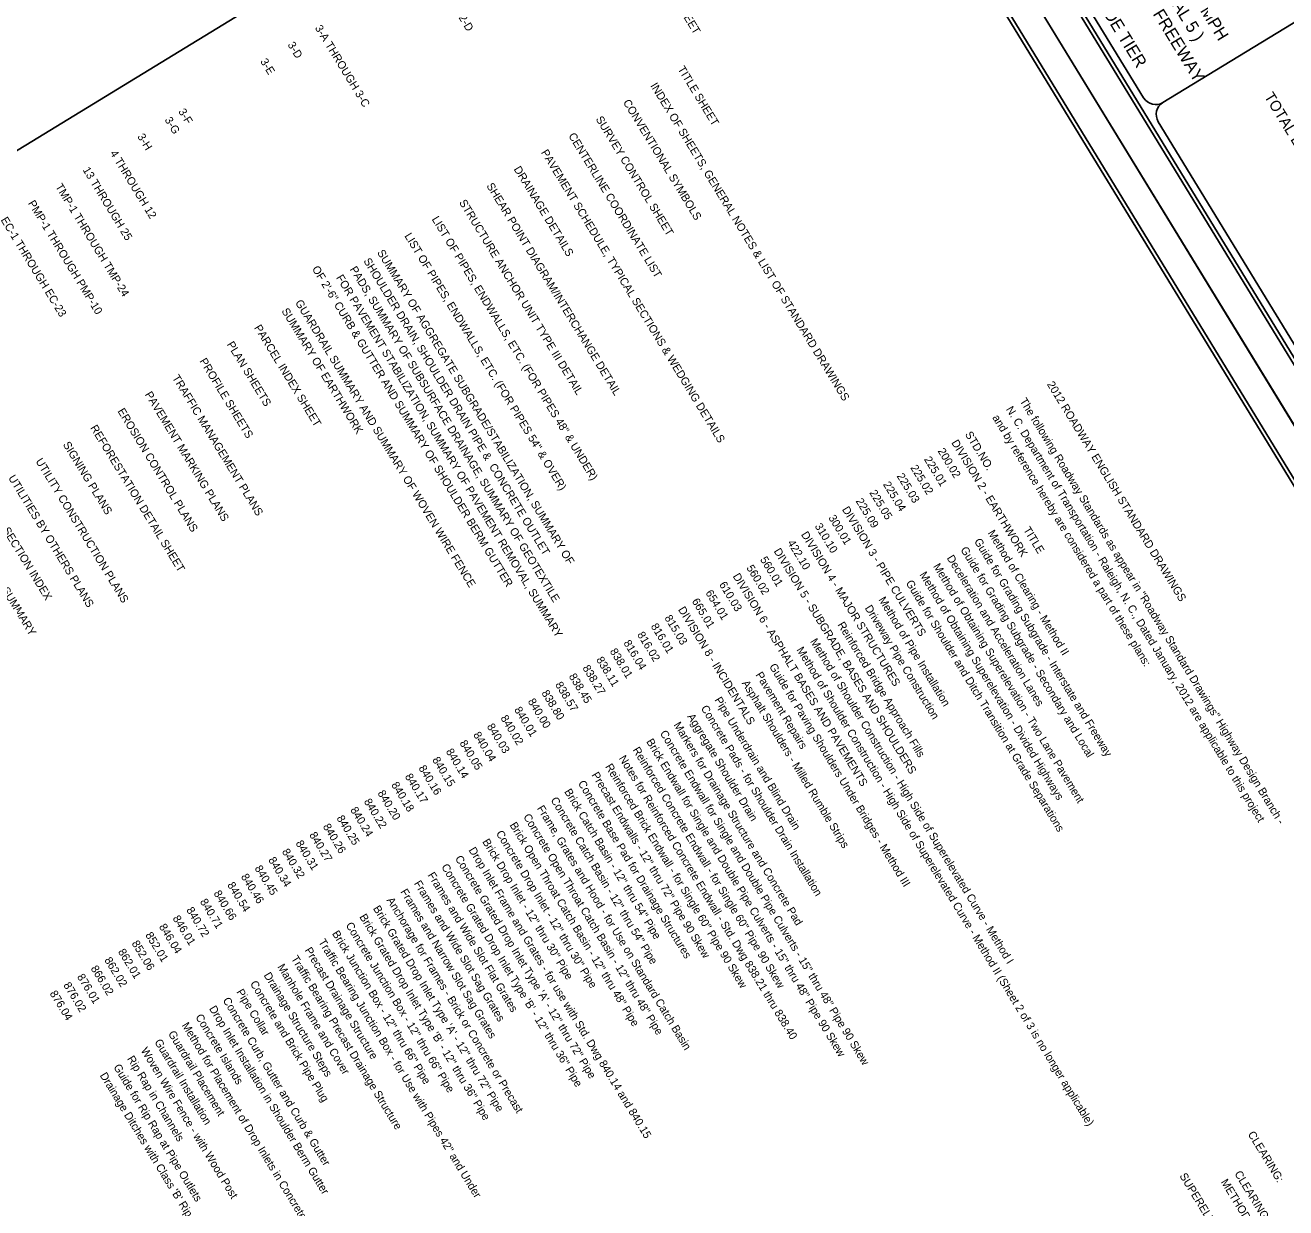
# Model space of a CAD drawing. Extents: x 1750583 to 1791140, y 783580 to 827376.
# Drawn here: x 1765888 to 1775731, y 806485 to 815720 of the extents above; entities that cross this region are included whole.
import ezdxf

# ---------------------------------------------------------------- set-up
doc = ezdxf.new("R2010")
doc.units = 0
for name, color, linetype in [('Prop Dimension Text', 7, 'Continuous'), ('Sheet Cutting Line CELL', 7, 'Continuous'), ('Sheet Data Field CELL', 7, 'Continuous'), ('Sheet Plan CELL', 7, 'Continuous'), ('Sheet Plot Border Inside CELL', 7, 'Continuous'), ('Sheet Plot Border Outside CELL', 7, 'Continuous'), ('Sheet Symbology CELL', 7, 'Continuous'), ('Sheet Title CELL', 7, 'Continuous')]:
    doc.layers.add(name, color=color, linetype=linetype)

msp = doc.modelspace()

# ---------------------------------------------------------------- linework, layer by layer
at = {"layer": 'Sheet Cutting Line CELL'}
for p, q in [((1771176.2, 820157.4), (1780824.8, 804365.9)), ((1780822, 804370.5), (1771176.2, 820157.4))]:
    msp.add_line(p, q, dxfattribs=at)
at = {"layer": 'Sheet Plan CELL'}
msp.add_lwpolyline([(1780513.6, 804401), (1771919.2, 818467.1), (1762073, 812451), (1770667.3, 798385)], close=True, dxfattribs=at)
at = {"layer": 'Sheet Plot Border Inside CELL'}
for points in [[(1771461.1, 820164), (1781009.5, 804536.6), (1790903.5, 810581.9), (1781355.2, 826209.3)], [(1761170, 813876.1), (1770715.5, 798253.4), (1780608.6, 804298.1), (1771063.2, 819920.9)]]:
    msp.add_lwpolyline(points, close=True, dxfattribs=at)
at = {"layer": 'Sheet Plot Border Outside CELL'}
for points in [[(1791139.8, 810668.3), (1781491.2, 826459.8), (1771176.2, 820157.4), (1780824.8, 804365.9)], [(1760908, 813883.5), (1770553.7, 798096.7), (1780822, 804370.5), (1771176.2, 820157.4)]]:
    msp.add_lwpolyline(points, close=True, dxfattribs=at)
at = {"layer": 'Sheet Title CELL'}
msp.add_line((1776271.7, 816033.2), (1774771.3, 815116.5), dxfattribs=at)
for points in [[(1772424.7, 818640.7), (1780904.5, 804762.2)], [(1773789.5, 816512.7), (1774620.3, 815152.9)], [(1774734.7, 814965.3), (1776912, 811401.9)]]:
    msp.add_lwpolyline(points, dxfattribs=at)
for centre, start, end in [((1774714.5, 815210.4), 211.42495, 301.42495), ((1774829.1, 815022.9), 121.42495, 211.42495)]:
    msp.add_arc(centre, 109.9, start, end, dxfattribs=at)

# ---------------------------------------------------------------- texts
at = {"layer": 'Prop Dimension Text'}
for s, p in [('SHEET NUMBER                            SHEET', (1770280.9, 817002.1)), ('2 THROUGH 2-D', (1769000.9, 816220)), ('3-A THROUGH 3-C', (1768147.6, 815698.7)), ('3-D', (1767934.3, 815568.3)), ('3-E', (1767720.9, 815438)), ('TITLE SHEET', (1770980, 815378.5)), ('INDEX OF SHEETS, GENERAL NOTES & LIST OF STANDARD DRAWINGS', (1770766.7, 815248.1)), ('3-F', (1767081, 815046.9)), ('CONVENTIONAL SYMBOLS', (1770553.3, 815117.8)), ('3-G', (1766974.3, 814981.8)), ('SURVEY CONTROL SHEET', (1770340, 814987.4)), ('3-H', (1766761, 814851.4)), ('CENTERLINE COORDINATE LIST', (1770126.7, 814857.1)), ('4 THROUGH 12', (1766547.6, 814721.1)), ('PAVEMENT SCHEDULE, TYPICAL SECTIONS & WEDGING DETAILS', (1769913.4, 814726.7)), ('13 THROUGH 25', (1766334.3, 814590.7)), ('DRAINAGE DETAILS', (1769700, 814596.4)), ('TMP-1 THROUGH TMP-24', (1766121, 814460.4)), ('SHEAR POINT DIAGRAM/INTERCHANGE DETAIL', (1769486.7, 814466)), ('PMP-1 THROUGH PMP-10', (1765907.6, 814330)), ('STRUCTURE ANCHOR UNIT TYPE III DETAIL', (1769273.4, 814335.7)), ('EC-1 THROUGH EC-23', (1765694.3, 814199.7)), ('LIST OF PIPES, ENDWALLS, ETC. (FOR PIPES 48" & UNDER)', (1769060, 814205.3)), ('LIST OF PIPES, ENDWALLS, ETC. (FOR PIPES 54" & OVER)', (1768846.7, 814075)), ('SHOULDER DRAIN, SHOULDER DRAIN PIPE &  CONCRETE OUTLET ', (1768526.7, 813879.5)), ('SUMMARY OF AGGREGATE SUBGRADE/STABILIZATION, SUMMARY OF ', (1768633.4, 813944.7)), ('    OF 2\'-6" CURB & GUTTER AND SUMMARY OF SHOULDER BERM GUTTER ', (1768076.4, 813897.3)), ('PADS, SUMMARY OF SUBSURFACE DRAINAGE, SUMMARY OF GEOTEXTILE ', (1768420, 813814.3)), ('FOR PAVEMENT STABILIZATION, SUMMARY OF PAVEMENT REMOVAL, SUMMARY ', (1768313.4, 813749.1)), ('SUMMARY OF EARTHWORK', (1767886.7, 813488.5)), ('GUARDRAIL SUMMARY AND SUMMARY OF WOVEN WIRE FENCE', (1767993.4, 813553.6)), ('PARCEL INDEX SHEET', (1767673.4, 813358.1)), ('PLAN SHEETS', (1767460, 813227.8)), ('PROFILE SHEETS', (1767246.7, 813097.4)), ('TRAFFIC MANAGEMENT PLANS', (1767033.4, 812967.1)), ('2012 ROADWAY ENGLISH STANDARD DRAWINGS', (1773863.5, 812916.4)), ('PAVEMENT MARKING PLANS', (1766820.1, 812836.7)), ('The following Roadway Standards as appear in "Roadway Standard Drawings" Highway Design Branch -', (1773650.2, 812786.1)), ('EROSION CONTROL PLANS', (1766606.7, 812706.4)), ('N. C. Department of Transportation - Raleigh, N. C., Dated January, 2012 are applicable to this project', (1773543.5, 812720.9)), ('REFORESTATION DETAIL SHEET', (1766393.4, 812576)), ('and by reference hereby are considered a part of these plans:', (1773436.8, 812655.7)), ('STD.NO.                       TITLE', (1773223.5, 812525.4)), ('SIGNING PLANS', (1766180.1, 812445.7)), ('200.02', (1773010.2, 812395)), ('DIVISION 2 - EARTHWORK', (1773116.8, 812460.2)), ('UTILITY CONSTRUCTION PLANS', (1765966.7, 812315.3)), ('225.01', (1772903.5, 812329.9)), ('UTILITIES BY OTHERS PLANS', (1765753.4, 812185)), ('225.03', (1772690.2, 812199.5)), ('225.02', (1772796.9, 812264.7)), ('225.04', (1772583.5, 812134.3)), ('CROSS-SECTION INDEX', (1765540.1, 812054.7)), ('225.09', (1772370.2, 812004)), ('225.05', (1772476.9, 812069.2)), ('CROSS-SECTION SUMMARY', (1765326.7, 811924.3)), ('DIVISION 3 - PIPE CULVERTS', (1772263.5, 811938.8)), ('310.10', (1772050.2, 811808.5)), ('300.01', (1772156.9, 811873.7)), ('DIVISION 4 - MAJOR STRUCTURES', (1771943.5, 811743.3)), ('Method of Clearing - Method II', (1773401.2, 811755)), ('DIVISION 5 - SUBGRADE, BASES AND SHOULDERS', (1771730.2, 811613)), ('422.10', (1771836.9, 811678.1)), ('Guide for Grading Subgrade - Secondary and Local', (1773187.9, 811624.7)), ('Guide for Grading Subgrade - Interstate and Freeway', (1773294.6, 811689.9)), ('560.01', (1771623.5, 811547.8)), ('Method of Obtaining Superelevation - Two Lane Pavement', (1772974.6, 811494.4)), ('Deceleration and Acceleration Lanes', (1773081.2, 811559.5)), ('DIVISION 6 - ASPHALT BASES AND PAVEMENTS', (1771410.2, 811417.4)), ('560.02', (1771516.9, 811482.6)), ('Method of Obtaining Superelevation - Divided Highways', (1772867.9, 811429.2)), ('610.03', (1771303.5, 811352.3)), ('Guide for Shoulder and Ditch Transition at Grade Separations', (1772761.2, 811364)), ('665.01', (1771090.2, 811221.9)), ('654.01', (1771196.9, 811287.1)), ('Method of Pipe Installation ', (1772547.9, 811233.7)), ('DIVISION 8 - INCIDENTALS', (1770983.5, 811156.8)), ('Driveway Pipe Construction', (1772441.2, 811168.5)), ('816.01', (1770770.2, 811026.4)), ('815.03', (1770876.9, 811091.6)), ('Reinforced Bridge Approach Fills', (1772227.9, 811038.1)), ('816.02', (1770663.5, 810961.2)), ('Method of Shoulder Construction - High Side of Superelevated Curve - Method I', (1772014.6, 810907.8)), ('838.01', (1770450.2, 810830.9)), ('816.04', (1770556.9, 810896.1)), ('Method of Shoulder Construction - High Side of Superelevated Curve - Method II (Sheet 2 of 3 is no longer applicable)', (1771907.9, 810842.6)), ('838.11', (1770343.5, 810765.7)), ('Guide for Paving Shoulders Under Bridges - Method III', (1771694.6, 810712.3)), ('838.45', (1770130.2, 810635.4)), ('838.27', (1770236.9, 810700.5)), ('Pavement Repairs', (1771587.9, 810647.1)), ('838.57', (1770023.5, 810570.2)), ('Asphalt Shoulders - Milled Rumble Strips', (1771481.2, 810581.9)), ('840.00', (1769810.2, 810439.9)), ('838.80', (1769916.9, 810505)), ('Pipe Underdrain and Blind Drain', (1771267.9, 810451.6)), ('840.01', (1769703.6, 810374.7)), ('Concrete Pads - for Shoulder Drain Installation', (1771161.2, 810386.4)), ('840.03', (1769490.2, 810244.3)), ('840.02', (1769596.9, 810309.5)), ('Markers for Drainage Structure and Concrete Pad', (1770947.9, 810256.1)), ('Aggregate Shoulder Drain', (1771054.6, 810321.2)), ('840.04', (1769383.6, 810179.2)), ('Brick Endwall for Single and Double Pipe Culverts - 15" thru 48" Pipe 90 Skew', (1770734.6, 810125.7)), ('Concrete Endwall for Single and Double Pipe Culverts - 15" thru 48" Pipe 90 Skew', (1770841.2, 810190.9)), ('840.14', (1769170.2, 810048.8)), ('840.05', (1769276.9, 810114)), ('Reinforced Concrete Endwall - for Single 60" Pipe 90 Skew', (1770627.9, 810060.6)), ('840.15', (1769063.6, 809983.6)), ('Reinforced Brick Endwall - for Single 60" Pipe 90 Skew', (1770414.6, 809930.2)), ('Notes for Reinforced Concrete Endwall - Std. Dwg 838.21 thru 838.40', (1770521.2, 809995.4)), ('840.17', (1768850.2, 809853.3)), ('840.16', (1768956.9, 809918.5)), ('Precast Endwalls - 12" thru 72" Pipe 90 Skew', (1770307.9, 809865)), ('840.18', (1768743.6, 809788.1)), ('Brick Catch Basin - 12" thru 54" Pipe', (1770094.6, 809734.7)), ('Concrete Base Pad for Drainage Structures', (1770201.3, 809799.9)), ('840.22', (1768530.2, 809657.8)), ('840.20', (1768636.9, 809723)), ('Concrete Catch Basin - 12" thru 54" Pipe', (1769987.9, 809669.5)), ('840.25', (1768316.9, 809527.4)), ('840.24', (1768423.6, 809592.6)), ('Concrete Open Throat Catch Basin - 12" thru 48" Pipe', (1769774.6, 809539.2)), ('Frame, Grates and Hood - for Use on Standard Catch Basin', (1769881.3, 809604.3)), ('840.26', (1768210.2, 809462.3)), ('Brick Open Throat Catch Basin - 12" thru 48" Pipe', (1769667.9, 809474)), ('840.31', (1767996.9, 809331.9)), ('840.27', (1768103.6, 809397.1)), ('Brick Drop Inlet - 12" thru 30" Pipe', (1769454.6, 809343.7)), ('Concrete Drop Inlet - 12" thru 30" Pipe', (1769561.3, 809408.8)), ('840.32', (1767890.2, 809266.7)), ('Drop Inlet Frame and Grates - for use with Std. Dwg 840.14 and 840.15', (1769347.9, 809278.5)), ('840.45', (1767676.9, 809136.4)), ('840.34', (1767783.6, 809201.6)), ('Concrete Grated Drop Inlet Type \'B\' - 12" thru 36" Pipe', (1769134.6, 809148.1)), ('Concrete Grated Drop Inlet Type \'A\' - 12" thru 72" Pipe', (1769241.3, 809213.3)), ('840.46', (1767570.2, 809071.2)), ('Frames and Wide Slot Flat Grates', (1769027.9, 809083)), ('840.66', (1767356.9, 808940.9)), ('840.54', (1767463.6, 809006.1)), ('Frames and Narrow Slot Sag Grates', (1768814.6, 808952.6)), ('Frames and Wide Slot Sag Grates', (1768921.3, 809017.8)), ('840.71', (1767250.2, 808875.7)), ('Anchorage for Frames - Brick or Concrete or Precast', (1768707.9, 808887.4)), ('846.01', (1767036.9, 808745.4)), ('840.72', (1767143.6, 808810.5)), ('Brick Grated Drop Inlet Type \'B\' - 12" thru 36" Pipe', (1768494.6, 808757.1)), ('Brick Grated Drop Inlet Type \'A\' - 12" thru 72" Pipe', (1768601.3, 808822.3)), ('846.04', (1766930.2, 808680.2)), ('Concrete Junction Box - 12" thru 66" Pipe', (1768387.9, 808691.9)), ('852.06', (1766716.9, 808549.8)), ('852.01', (1766823.6, 808615)), ('Traffic Bearing Junction Box - for Use with Pipes 42" and Under', (1768174.6, 808561.6)), ('Brick Junction Box - 12" thru 66" Pipe', (1768281.3, 808626.8)), ('862.01', (1766610.3, 808484.7)), ('Precast Drainage Structure', (1768067.9, 808496.4)), ('866.02', (1766396.9, 808354.3)), ('862.02', (1766503.6, 808419.5)), ('Manhole Frame and Cover', (1767854.6, 808366.1)), ('Traffic Bearing Precast Drainage Structure', (1767961.3, 808431.2)), ('876.01', (1766290.3, 808289.2)), ('Drainage Structure Steps', (1767747.9, 808300.9)), ('876.04', (1766076.9, 808158.8)), ('876.02', (1766183.6, 808224)), ('Pipe Collar', (1767534.6, 808170.5)), ('Concrete and Brick Pipe Plug', (1767641.3, 808235.7)), ('Concrete Curb, Gutter and Curb & Gutter', (1767428, 808105.4)), ('Concrete Islands', (1767214.6, 807975)), ('Drop Inlet Installation in Shoulder Berm Gutter', (1767321.3, 808040.2)), ('Method for Placement of Drop Inlets in Concrete Islands', (1767108, 807909.9)), ('Guardrail Installation', (1766894.6, 807779.5)), ('Guardrail Placement', (1767001.3, 807844.7)), ('Woven Wire Fence - with Wood Post', (1766788, 807714.3)), ('Guide for Rip Rap at Pipe Outlets', (1766574.6, 807584)), ('Rip Rap in Channels', (1766681.3, 807649.2)), ("Drainage Ditches with Class 'B' Rip Rap", (1766468, 807518.8)), ('CLEARING:  ', (1775431.7, 807059.8)), ('SUPERELEVATION:  ', (1774898.4, 806733.9)), ('         METHOD II.', (1775111.7, 806864.3)), ('         CLEARING ON THIS PROJECT SHALL BE PERFORMED TO THE LIMITS ESTABLISHED BY ', (1775218.4, 806929.5))]:
    msp.add_text(s, height=62.5, rotation=301.42495, dxfattribs=at).set_placement(p)
at = {"layer": 'Sheet Data Field CELL'}
for s, height, p in [('STATEWIDE TIER', 96.25, (1774006.9, 816299)), ('+ DUAL 5 )', 96.25, (1774685.4, 816131.6)), ('MPH', 96.25, (1775058.9, 815833.7)), ('FREEWAY       ', 96.25, (1774689.5, 815808.4)), ('      TOTAL LENGTH TIP PROJECT R-2612B', 83.997, (1775461, 815323.7))]:
    msp.add_text(s, height=height, rotation=301.42495, dxfattribs=at).set_placement(p)
at = {"layer": 'Sheet Symbology CELL'}
for s, height, p in [('CONVENTIONAL  PLAN SHEET SYMBOLS', 299.204, (1763093.3, 807871.1)), ('STATE OF NORTH CAROLINA', 235.609, (1764731.2, 806508.8))]:
    msp.add_text(s, height=height, rotation=301.42495, dxfattribs=at).set_placement(p)

doc.saveas('drawing.dxf')
